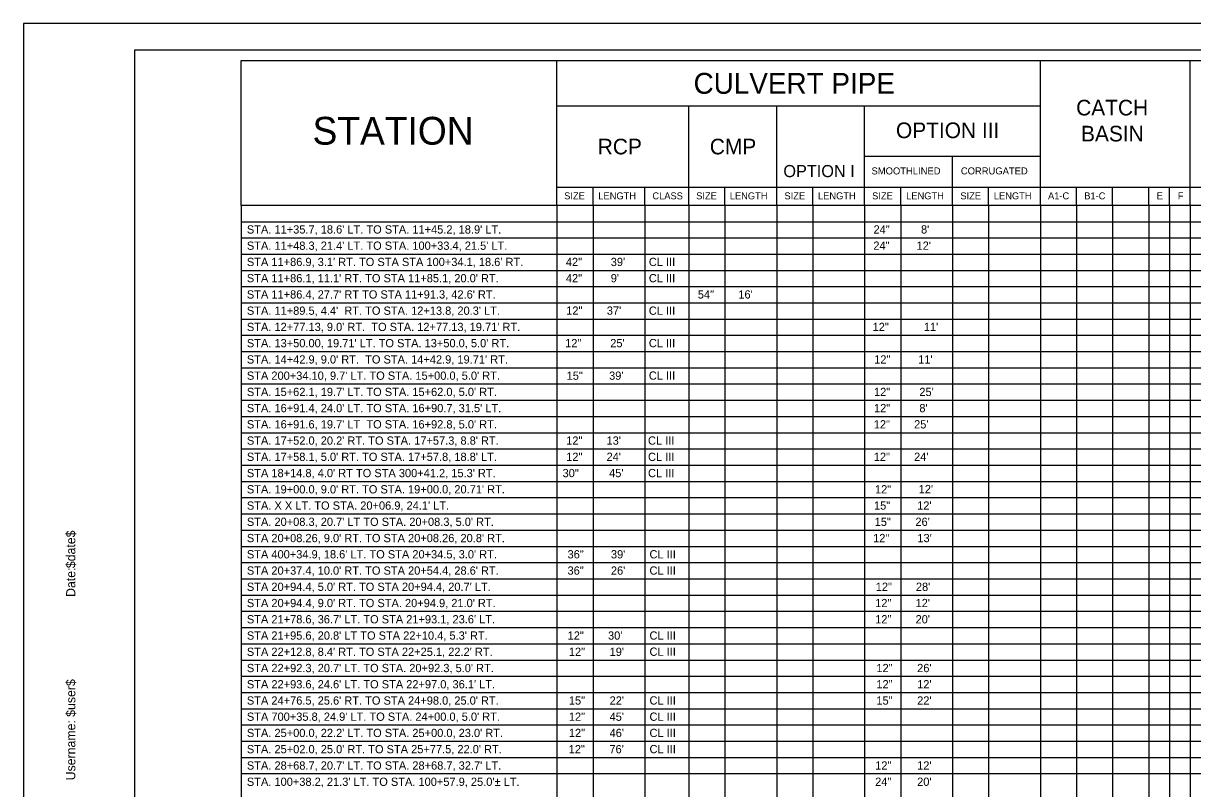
# Model space of a CAD drawing. Extents: x -0.13 to 2.7, y -0.05 to 1.78.
# Drawn here: x -0.135 to 1.283, y 0.854 to 1.782 of the extents above; entities that cross this region are included whole.
import ezdxf

# ---------------------------------------------------------------- set-up
doc = ezdxf.new("R2010")
doc.units = 0
for name, color, linetype in [('ANNOTATION', 7, 'Continuous'), ('BORDER', 7, 'Continuous'), ('PLOT BOUNDARY', 7, 'Continuous')]:
    doc.layers.add(name, color=color, linetype=linetype)

msp = doc.modelspace()

# ---------------------------------------------------------------- linework, layer by layer
at = {"layer": 'ANNOTATION'}
msp.add_line((0.5559, 1.5616), (0.5559, 1.5836), dxfattribs=at)
at = {"layer": 'BORDER'}
for p, q in [((2.6667, 1.75), (0, 1.75)), ((0, 1.75), (0, 0)), ((0.512, 1.6825), (0.512, 1.7373)), ((1.0982, 1.6825), (1.0982, 1.7373)), ((1.2798, 1.6825), (1.2798, 1.7373)), ((0.512, 1.6214), (0.512, 1.6825)), ((0.512, 1.6825), (0.5559, 1.6825)), ((0.5559, 1.6825), (0.6186, 1.6825)), ((0.6186, 1.6825), (0.6719, 1.6825)), ((0.6719, 1.6214), (0.6719, 1.6825)), ((0.6719, 1.6825), (0.7158, 1.6825)), ((0.7158, 1.6825), (0.7785, 1.6825)), ((0.7785, 1.6214), (0.7785, 1.6825)), ((0.7785, 1.6825), (0.8223, 1.6825)), ((0.8223, 1.6825), (0.9289, 1.6825)), ((0.885, 1.5836), (0.885, 1.6825)), ((0.9289, 1.6825), (1.0982, 1.6825)), ((1.0982, 1.6214), (1.0982, 1.6825)), ((1.2798, 1.6214), (1.2798, 1.6825)), ((0.512, 1.5836), (0.512, 1.6214)), ((0.6719, 1.5836), (0.6719, 1.6214)), ((0.7785, 1.5836), (0.7785, 1.6214)), ((0.885, 1.6214), (0.9289, 1.6214)), ((0.9289, 1.6214), (1.0354, 1.6214)), ((0.9916, 1.5616), (0.9916, 1.6214)), ((1.0354, 1.6214), (1.0982, 1.6214)), ((1.0982, 1.5836), (1.0982, 1.6214)), ((1.2798, 1.5836), (1.2798, 1.6214)), ((0.512, 1.5616), (0.512, 1.5836)), ((0.512, 1.5836), (0.5559, 1.5836)), ((0.5559, 1.5836), (0.6186, 1.5836)), ((0.6186, 1.5616), (0.6186, 1.5836)), ((0.6186, 1.5836), (0.6719, 1.5836)), ((0.6719, 1.5616), (0.6719, 1.5836)), ((0.6719, 1.5836), (0.7158, 1.5836)), ((0.7158, 1.5616), (0.7158, 1.5836)), ((0.7158, 1.5836), (0.7785, 1.5836)), ((0.7785, 1.5616), (0.7785, 1.5836)), ((0.7785, 1.5836), (0.8223, 1.5836)), ((0.8223, 1.5616), (0.8223, 1.5836)), ((0.8223, 1.5836), (0.885, 1.5836)), ((0.885, 1.5616), (0.885, 1.5836)), ((0.885, 1.5836), (0.9289, 1.5836)), ((0.9289, 1.5616), (0.9289, 1.5836)), ((0.9289, 1.5836), (0.9916, 1.5836)), ((0.9916, 1.5836), (1.0354, 1.5836)), ((1.0354, 1.5616), (1.0354, 1.5836)), ((1.0354, 1.5836), (1.0982, 1.5836)), ((1.0982, 1.5616), (1.0982, 1.5836)), ((1.0982, 1.5836), (1.142, 1.5836)), ((1.142, 1.5616), (1.142, 1.5836)), ((1.142, 1.5836), (1.1858, 1.5836)), ((1.1858, 1.5616), (1.1858, 1.5836)), ((1.1858, 1.5836), (1.2298, 1.5836)), ((1.2298, 1.5616), (1.2298, 1.5836)), ((1.2298, 1.5836), (1.2548, 1.5836)), ((1.2548, 1.5616), (1.2548, 1.5836)), ((1.2548, 1.5836), (1.2798, 1.5836)), ((1.2798, 1.5616), (1.2798, 1.5836)), ((1.2798, 1.5836), (1.3237, 1.5836)), ((0.512, 1.5616), (0.512, 0.0065)), ((0.5559, 1.5616), (0.5559, 0.0065)), ((0.6186, 1.5616), (0.6186, 0.0065)), ((0.6719, 1.5616), (0.6719, 0.0065)), ((0.7158, 1.5616), (0.7158, 0.0065)), ((0.7785, 1.5616), (0.7785, 0.0065)), ((0.8223, 1.5616), (0.8223, 0.0065)), ((0.885, 1.5616), (0.885, 0.0065)), ((0.9289, 1.5616), (0.9289, 0.0065)), ((0.9916, 1.5616), (0.9916, 0.0065)), ((1.0354, 1.5616), (1.0354, 0.0065)), ((1.0982, 1.5616), (1.0982, 0.0065)), ((1.142, 1.5616), (1.142, 0.0065)), ((1.1858, 1.5616), (1.1858, 0.0065)), ((1.2298, 1.5616), (1.2298, 0.0065)), ((1.2548, 1.5616), (1.2548, 0.0065)), ((1.2798, 1.5616), (1.2798, 0.0065)), ((0.1293, 1.5419), (2.3707, 1.5419)), ((0.1293, 1.5223), (2.3707, 1.5223)), ((0.1293, 1.5026), (2.3707, 1.5026)), ((0.1293, 1.4829), (2.3707, 1.4829)), ((0.1293, 1.4632), (2.3707, 1.4632)), ((0.1293, 1.4435), (2.3707, 1.4435)), ((0.1293, 1.4238), (2.3707, 1.4238)), ((0.1293, 1.4041), (2.3707, 1.4041)), ((0.1293, 1.3845), (2.3707, 1.3845)), ((0.1293, 1.3648), (2.3707, 1.3648)), ((0.1293, 1.3451), (2.3707, 1.3451)), ((0.1293, 1.3254), (2.3707, 1.3254)), ((0.1293, 1.3057), (2.3707, 1.3057)), ((0.1293, 1.286), (2.3707, 1.286)), ((0.1293, 1.2664), (2.3707, 1.2664)), ((0.1293, 1.2467), (2.3707, 1.2467)), ((0.1293, 1.227), (2.3707, 1.227)), ((0.1293, 1.2073), (2.3707, 1.2073)), ((0.1293, 1.1876), (2.3707, 1.1876)), ((0.1293, 1.1679), (2.3707, 1.1679)), ((0.1293, 1.1482), (2.3707, 1.1482)), ((0.1293, 1.1286), (2.3707, 1.1286)), ((0.1293, 1.1089), (2.3707, 1.1089)), ((0.1293, 1.0892), (2.3707, 1.0892)), ((0.1293, 1.0695), (2.3707, 1.0695)), ((0.1293, 1.0498), (2.3707, 1.0498)), ((0.1293, 1.0301), (2.3707, 1.0301)), ((0.1293, 1.0104), (2.3707, 1.0104)), ((0.1293, 0.9908), (2.3707, 0.9908)), ((0.1293, 0.9711), (2.3707, 0.9711)), ((0.1293, 0.9514), (2.3707, 0.9514)), ((0.1293, 0.9317), (2.3707, 0.9317)), ((0.1293, 0.912), (2.3707, 0.912)), ((0.1293, 0.8923), (2.3707, 0.8923)), ((0.1293, 0.8727), (2.3707, 0.8727))]:
    msp.add_line(p, q, dxfattribs=at)
msp.add_lwpolyline([(0.1293, 1.7373), (2.3707, 1.7373), (2.3707, 1.5616), (0.1293, 1.5616)], close=True, dxfattribs=at)
msp.add_lwpolyline([(0.1293, 1.5616), (0.1293, 0.0065), (2.3707, 0.0065), (2.3707, 1.5616)], dxfattribs=at)
at = {"layer": 'PLOT BOUNDARY'}
msp.add_lwpolyline([(-0.1349, -0.051), (2.6984, -0.051), (2.6984, 1.7823), (-0.1349, 1.7823)], close=True, dxfattribs=at)

# ---------------------------------------------------------------- texts
at = {"layer": 'ANNOTATION'}
for s, p in [("STA. 11+35.7, 18.6' LT. TO STA. 11+45.2, 18.9' LT.", (0.1361, 1.5275)), ('24"', (0.8959, 1.5275)), ("8'", (0.9535, 1.5275)), ("STA. 11+48.3, 21.4' LT. TO STA. 100+33.4, 21.5' LT.", (0.1361, 1.5078)), ('24"', (0.8957, 1.5078)), ("12'", (0.9481, 1.5078)), ("STA 11+86.9, 3.1' RT. TO STA STA 100+34.1, 18.6' RT.", (0.1361, 1.4881)), ('42"', (0.5229, 1.4881)), ("39'", (0.5773, 1.4881)), ('CL III', (0.6235, 1.4881)), ("STA 11+86.1, 11.1' RT. TO STA 11+85.1, 20.0' RT.", (0.1361, 1.4684)), ('42"', (0.5229, 1.4684)), ("9'", (0.5773, 1.4684)), ('CL III', (0.6235, 1.4684)), ("STA 11+86.4, 27.7' RT TO STA 11+91.3, 42.6' RT.", (0.1361, 1.4487)), ('54"', (0.6829, 1.4487)), ("16'", (0.732, 1.4487)), ("STA. 11+89.5, 4.4'  RT. TO STA. 12+13.8, 20.3' LT.", (0.1361, 1.429)), ('12"', (0.5233, 1.4291)), ("37'", (0.5725, 1.4291)), ('CL III', (0.6235, 1.429)), ("STA. 12+77.13, 9.0' RT.  TO STA. 12+77.13, 19.71' RT.", (0.1361, 1.4093)), ('12"', (0.8948, 1.4093)), ("11'", (0.9569, 1.4093)), ("STA. 13+50.00, 19.71' LT. TO STA. 13+50.0, 5.0' RT. ", (0.1361, 1.3896)), ('12"', (0.522, 1.3896)), ("25'", (0.5767, 1.3896)), ('CL III', (0.6235, 1.3897)), ("STA. 14+42.9, 9.0' RT.  TO STA. 14+42.9, 19.71' RT.", (0.1361, 1.3699)), ('12"', (0.8967, 1.3699)), ("11'", (0.9501, 1.3699)), ("STA 200+34.10, 9.7' LT. TO STA. 15+00.0, 5.0' RT.", (0.1361, 1.3502)), ('15"', (0.5238, 1.3502)), ("39'", (0.5753, 1.3502)), ('CL III', (0.6235, 1.3503)), ("STA. 15+62.1, 19.7' LT. TO STA. 15+62.0, 5.0' RT.", (0.1361, 1.3305)), ('12" ', (0.8965, 1.3305)), ("25'", (0.9515, 1.3305)), ("STA. 16+91.4, 24.0' LT. TO STA. 16+90.7, 31.5' LT.", (0.1361, 1.3109)), ('12" ', (0.8965, 1.3109)), ("8'", (0.9515, 1.3109)), ("STA. 16+91.6, 19.7' LT  TO STA. 16+92.8, 5.0' RT.", (0.1361, 1.2912)), ('12"', (0.8962, 1.2912)), ("25'", (0.9451, 1.2912)), ("STA. 17+52.0, 20.2' RT. TO STA. 17+57.3, 8.8' RT.", (0.1361, 1.2715)), ('12"', (0.5233, 1.2715)), ("13'", (0.5722, 1.2715)), ('CL III', (0.6225, 1.2715)), ("STA. 17+58.1, 5.0' RT. TO STA. 17+57.8, 18.8' LT.", (0.1361, 1.2518)), ('12"', (0.5233, 1.2518)), ("24'", (0.5722, 1.2518)), ('CL III', (0.6225, 1.2518)), ('12"', (0.8962, 1.2518)), ("24'", (0.9451, 1.2518)), ("STA 18+14.8, 4.0' RT TO STA 300+41.2, 15.3' RT.", (0.1361, 1.2321)), ('30"', (0.5189, 1.2321)), ("45'", (0.5753, 1.2321)), ('CL III', (0.6225, 1.2321)), ("STA. 19+00.0, 9.0' RT. TO STA. 19+00.0, 20.71' RT.", (0.1361, 1.2124)), ('12"', (0.8977, 1.2124)), ("12'", (0.9507, 1.2127)), ("STA. X X LT. TO STA. 20+06.9, 24.1' LT.", (0.1361, 1.1927)), ('15"', (0.8965, 1.1927)), ("12'", (0.9488, 1.1927)), ("STA. 20+08.3, 20.7' LT TO STA. 20+08.3, 5.0' RT.", (0.1361, 1.173)), ('15"', (0.8973, 1.173)), ("26'", (0.9467, 1.173)), ("STA 20+08.26, 9.0' RT. TO STA 20+08.26, 20.8' RT.", (0.1361, 1.1533)), ('12"', (0.8954, 1.1533)), ("13'", (0.9491, 1.1533)), ("STA 400+34.9, 18.6' LT. TO STA 20+34.5, 3.0' RT.", (0.1361, 1.1336)), ('36"', (0.5249, 1.1336)), ("39'", (0.5775, 1.1336)), ('CL III', (0.6243, 1.1336)), ("STA 20+37.4, 10.0' RT. TO STA 20+54.4, 28.6' RT.", (0.1361, 1.1139)), ('36"', (0.5249, 1.1139)), ("26'", (0.5775, 1.1139)), ('CL III', (0.6243, 1.1139)), ("STA 20+94.4, 5.0' RT. TO STA 20+94.4, 20.7' LT.", (0.1361, 1.0942)), ('12" ', (0.8986, 1.0942)), ("28'", (0.9473, 1.0942)), ("STA 20+94.4, 9.0' RT. TO STA. 20+94.9, 21.0' RT.", (0.1361, 1.0745)), ('12" ', (0.8979, 1.0745)), ("12'", (0.9469, 1.0745)), ("STA 21+78.6, 36.7' LT. TO STA 21+93.1, 23.6' LT.", (0.1361, 1.0548)), ('12" ', (0.8979, 1.0548)), ("20'", (0.9469, 1.0548)), ("STA 21+95.6, 20.8' LT TO STA 22+10.4, 5.3' RT.", (0.1361, 1.0351)), ('12" ', (0.525, 1.0351)), ("30'", (0.574, 1.0351)), ('CL III', (0.6243, 1.0351)), ("STA 22+12.8, 8.4' RT. TO STA 22+25.1, 22.2' RT.", (0.1361, 1.0154)), ('12" ', (0.5265, 1.0154)), ("19'", (0.5759, 1.0154)), ('CL III', (0.6243, 1.0155)), ("STA 22+92.3, 20.7' LT. TO STA. 20+92.3, 5.0' RT.", (0.1361, 0.9957)), ('12" ', (0.8994, 0.9957)), ("26'", (0.9488, 0.9957)), ("STA 22+93.6, 24.6' LT. TO STA 22+97.0, 36.1' LT.", (0.1361, 0.976)), ('12" ', (0.8994, 0.976)), ("12'", (0.9488, 0.976)), ("STA 24+76.5, 25.6' RT. TO STA 24+98.0, 25.0' RT.", (0.1361, 0.9563)), ('15"', (0.5265, 0.9563)), ("22'", (0.5759, 0.9563)), ('CL III', (0.6243, 0.9564)), ('15"', (0.8994, 0.9563)), ("22'", (0.9488, 0.9563)), ("STA 700+35.8, 24.9' LT. TO STA. 24+00.0, 5.0' RT.", (0.1361, 0.9367)), ('12" ', (0.5265, 0.9367)), ("45'", (0.5759, 0.9367)), ('CL III', (0.6243, 0.9367)), ("STA. 25+00.0, 22.2' LT. TO STA. 25+00.0, 23.0' RT.", (0.1361, 0.917)), ('12" ', (0.5265, 0.917)), ("46'", (0.5759, 0.917)), ('CL III', (0.6243, 0.917)), ("STA. 25+02.0, 25.0' RT. TO STA 25+77.5, 22.0' RT.", (0.1361, 0.8973)), ('12"', (0.5263, 0.8973)), ("76'", (0.5757, 0.8973)), ('CL III', (0.6243, 0.8974)), ("STA. 28+68.7, 20.7' LT. TO STA. 28+68.7, 32.7' LT.", (0.1361, 0.8775)), ('12" ', (0.8979, 0.8775)), ("12'", (0.9488, 0.8775)), ("STA. 100+38.2, 21.3' LT. TO STA. 100+57.9, 25.0'%%P LT.", (0.1361, 0.8578)), ('24"', (0.8979, 0.8578)), ("20'", (0.9488, 0.8578))]:
    msp.add_text(s, height=0.01, dxfattribs=at).set_placement(p)
at = {"layer": 'BORDER'}
for s, height, p in [('CULVERT PIPE', 0.025276, (0.6777, 1.697)), ('CATCH', 0.01896, (1.1416, 1.6707)), ('STATION', 0.0337, (0.2157, 1.6353)), ('OPTION III', 0.01896, (0.9231, 1.6432)), ('BASIN', 0.01896, (1.1475, 1.6392)), ('RCP', 0.01896, (0.5615, 1.6235)), ('CMP', 0.01896, (0.6974, 1.6235)), ('OPTION I', 0.01474, (0.7866, 1.5959)), ('SMOOTHLINED', 0.008531, (0.8935, 1.5992)), ('CORRUGATED', 0.00853, (1.0018, 1.5992)), ('SIZE', 0.00843, (0.5208, 1.569)), ('LENGTH', 0.00843, (0.5622, 1.569)), ('CLASS', 0.00843, (0.6278, 1.569)), ('SIZE', 0.00843, (0.6809, 1.569)), ('LENGTH', 0.00843, (0.7216, 1.569)), ('SIZE', 0.00843, (0.7879, 1.569)), ('LENGTH', 0.00843, (0.8286, 1.569)), ('SIZE', 0.00843, (0.8942, 1.569)), ('LENGTH', 0.00843, (0.9355, 1.569)), ('SIZE', 0.00843, (1.0012, 1.569)), ('LENGTH', 0.00843, (1.0418, 1.569)), ('A1-C', 0.00843, (1.1075, 1.569)), ('B1-C', 0.00843, (1.1514, 1.569)), ('E', 0.00843, (1.2393, 1.569)), ('F', 0.00843, (1.2649, 1.569))]:
    msp.add_text(s, height=height, dxfattribs=at).set_placement(p)
for s, p in [('$date$', (-0.0719, 1.1218)), ('Date:', (-0.0719, 1.0869)), ('$user$', (-0.0719, 0.9415)), ('Username:', (-0.0719, 0.8645))]:
    msp.add_text(s, height=0.01116, rotation=90, dxfattribs=at).set_placement(p)

doc.saveas('drawing.dxf')
